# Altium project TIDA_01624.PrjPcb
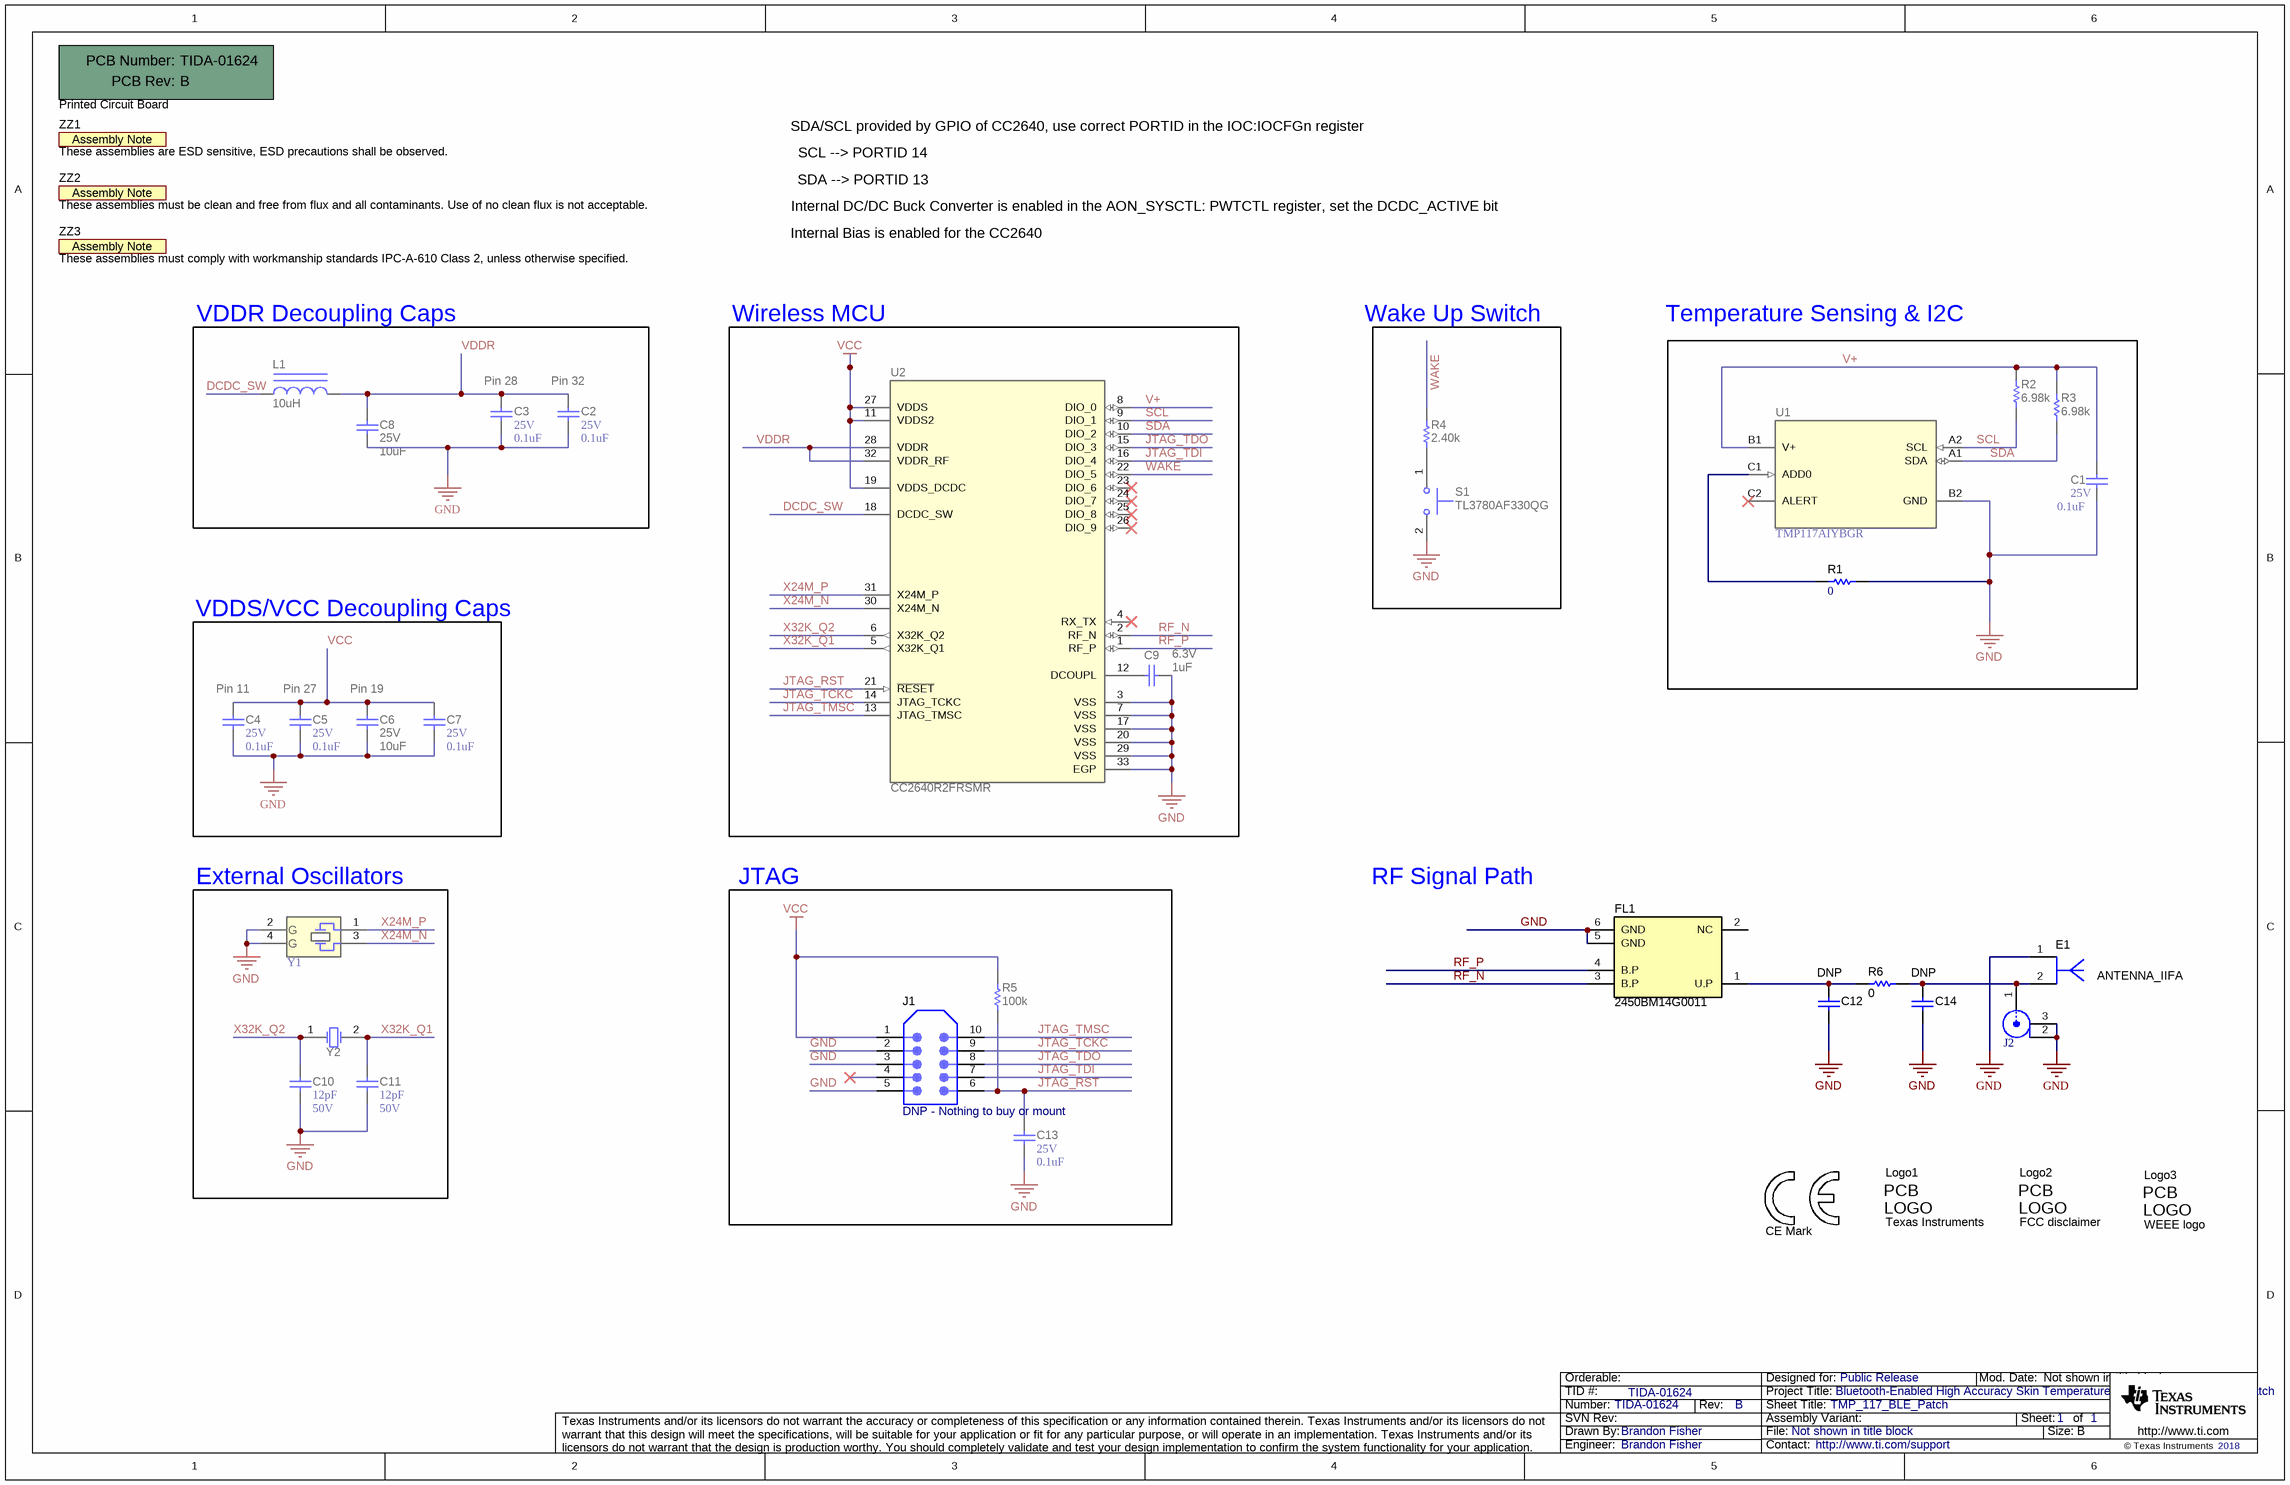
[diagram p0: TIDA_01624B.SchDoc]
CopyrightYear: 2018; PCB_Layout: Brandon Fisher; PCB_Rev: B; PRJ_Customer: Public Release; PRJ_Engineer: Brandon Fisher; PRJ_Number: TIDA-01624; PRJ_Title: Bluetooth-Enabled High Accuracy Skin Temperature Measurement Flex PCB Patch; SCH_Rev: B; TechSupport: http://www.ti.com/support; TID: TIDA-01624
1 sheet, 38 parts. Net scope: global (net labels, ports and power ports of the same name join across sheets).
Board file: TIDA_01624B.PcbDoc

## Sheet TIDA_01624B.SchDoc: TMP_117_BLE_Patch
size 431 x 279 mm; Date: Not shown in title block; ApprovedBy: Not shown in title block; CheckedBy: Not shown in title block; Author: Not shown in title block; CompanyName: Not shown in title block; DrawnBy: Brandon Fisher; Engineer: Not shown in title block; Organization: Not shown in title block; Address1: Not shown in title block; Address2: Not shown in title block; Address3: Not shown in title block; Address4: Not shown in title block; DocumentNumber: 1; Revision: Use project parameter SCH_Rev; SheetNumber: 1; SheetTotal: 1; PageSetup: Record=PageOptions¦CenterHorizontal=True¦CenterVertical=True¦PrintScale=1.00¦XCorrection=1.00¦YCorrection=1.00¦PrintKind=0¦BorderSize=5000000¦LeftOffset=0¦BottomOffset=0¦Orientation=2¦PaperLength=1000¦PaperWidth=1000¦Scale=100¦PaperSource=15¦PrintQuality=600¦MediaType=1¦DitherType=10¦PaperKind=Letter¦PrintScaleMode=1

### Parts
!PCB1  Printed Circuit Board  (mechanical)
C1  VDC_V: 25V  ValueDisplayed: 0.1uF  [0402]  (hidden comment: GRM155R71E104KE14D)
C2  VDC_V: 25V  ValueDisplayed: 0.1uF  [0402]  (hidden comment: GRM155R71E104KE14D)
C3  VDC_V: 25V  ValueDisplayed: 0.1uF  [0402]  (hidden comment: GRM155R71E104KE14D)
C4  VDC_V: 25V  ValueDisplayed: 0.1uF  [0402]  (hidden comment: GRM155R71E104KE14D)
C5  VDC_V: 25V  ValueDisplayed: 0.1uF  [0402]  (hidden comment: GRM155R71E104KE14D)
C6  VDC_V: 25V  ValueDisplayed: 10uF  [0603]  (hidden comment: C1608X5R1E106M080AC)
C7  VDC_V: 25V  ValueDisplayed: 0.1uF  [0402]  (hidden comment: GRM155R71E104KE14D)
C8  VDC_V: 25V  ValueDisplayed: 10uF  [0603]  (hidden comment: C1608X5R1E106M080AC)
C9  VDC_V: 6.3V  ValueDisplayed: 1uF  [0402]  (hidden comment: GRM152R60J105ME15D)
C10  ValueDisplayed: 12pF  VDC_V: 50V  [0201]  (hidden comment: Capacitor)
C11  ValueDisplayed: 12pF  VDC_V: 50V  [0201]  (hidden comment: Capacitor)
C12  DNP  [0201_033]
C13  VDC_V: 25V  ValueDisplayed: 0.1uF  [0402]  (hidden comment: GRM155R71E104KE14D)
C14  DNP  [0201_033]
E1  ANTENNA_IIFA  [ANTENNA_IIFA]  (net tie)
FL1  2450BM14G0011  [Johanson_2450BM14G0011]
J1  DNP - Nothing to buy or mount  [Tag_TC2050-NL]  (no BOM)
J2  U.FL-R-SMT-1(01)  [CONN_UFL-R-SMT-1]  (value not drawn)
L1  ValueDisplayed: 10uH  [0805_HV]  (hidden comment: CKS2125100M-T)
Logo1  Texas Instruments  [TI_Symbol_Overlay_Small]  (no BOM)
Logo2  FCC disclaimer  [FCC_disclaimer]  (no BOM)
Logo3  WEEE logo  [WEEE_Minimum]  (no BOM)
Logo4  CE Mark  [CE_Mark_5mm]  (no BOM)
R1  ValueDisplayed: 0  [0402L]  (hidden comment: RC0402JR-070RL)
R2  ValueDisplayed: 6.98k  [0603]  (hidden comment: RC0603FR-076K98L)
R3  ValueDisplayed: 6.98k  [0603]  (hidden comment: RC0603FR-076K98L)
R4  ValueDisplayed: 2.40k  [0402]  (hidden comment: ERJ-2RKF2401X)
R5  ValueDisplayed: 100k  [0402]  (hidden comment: ERJ-2RKF1003X)
R6  ValueDisplayed: 0  [0201]  (hidden comment: CRCW02010000Z0ED)
S1  TL3780AF330QG  [SW_TL3780]
U1  TMP117AIYBGR  [YBG0006AJAP]
U2  CC2640R2FRSMR  [RSM0032B_NV]
Y1  TSX-3225 24.0000MF15X-AC3  [EPSON_TSX-3225]  (value not drawn)
Y2  CM2012H32768DZFT  [CM2012H]  (value not drawn)
ZZ1  These assemblies are ESD sensitive, ESD precautions shall be observed.  [AssemblyNote]  (no BOM)
ZZ2  These assemblies must be clean and free from flux and all contaminants. Use of no clean flux is not acceptable.  [AssemblyNote]  (no BOM)
ZZ3  These assemblies must comply with workmanship standards IPC-A-610 Class 2, unless otherwise specified.  [AssemblyNote]  (no BOM)

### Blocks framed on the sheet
VDDR Decoupling Caps: C2 C3 C8 L1
Wireless MCU: C9 U2
Wake Up Switch: R4 S1
VDDS/VCC Decoupling Caps: C4-C7
External Oscillators: C10 C11 Y1 Y2
JTAG: C13 J1 R5

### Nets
GND: C1.2 C2.1 C3.1 C4.1 C5.1 C6.2 C7.2 C8.2 C9.1 C10.2 C11.2 C12.2 C13.2 C14.2 E1.1 FL1.5(GND) FL1.6(GND) J1.2 J1.3 J1.5 J2.2 J2.3 R1.2 S1.2 U1.B2(GND) U2.3(VSS) U2.7(VSS) U2.17(VSS) U2.20(VSS) U2.29(VSS) U2.33(EGP) Y1.2(GND) Y1.4(GND)
VCC: C4.2 C5.2 C6.1 C7.1 J1.1 R5.2 U2.11(VDDS2) U2.19(VDDS_DCDC) U2.27(VDDS)
DCDC_SW: L1.1 U2.18(DCDC_SW)
JTAG_RST: C13.1 J1.6 R5.1 U2.21(~{RESET})
JTAG_TCKC: J1.9 U2.14(JTAG_TCKC)
JTAG_TDI: J1.7 U2.16(DIO_4)
JTAG_TDO: J1.8 U2.15(DIO_3)
JTAG_TMSC: J1.10 U2.13(JTAG_TMSC)
RF_N: FL1.3(B.P) U2.2(RF_N)
RF_P: FL1.4(B.P) U2.1(RF_P)
SCL: R2.1 U1.A2(SCL) U2.9(DIO_1)
SDA: R3.1 U1.A1(SDA) U2.10(DIO_2)
V+: C1.1 R2.2 R3.2 U1.B1(V+) U2.8(DIO_0)
VDDR: C2.2 C3.2 C8.1 L1.2 U2.28(VDDR) U2.32(VDDR_RF)
WAKE: R4.1 U2.22(DIO_5)
X24M_N: U2.30(X24M_N) Y1.3
X24M_P: U2.31(X24M_P) Y1.1
X32K_Q1: C11.1 U2.5(X32K_Q1) Y2.2(OSC2)
X32K_Q2: C10.1 U2.6(X32K_Q2) Y2.1(OSC1)
NetC9_2: C9.2 U2.12(DCOUPL)
NetC12_1: C12.1 FL1.1(U.P) R6.1
NetC14_1: C14.1 E1.2 J2.1 R6.2
NetR1_1: R1.1 U1.C1(ADD0)
NetR4_2: R4.2 S1.1

Not connected (* = marked no-connect by the designer): FL1 2(NC); J1 4*; U1 C2(ALERT)*; U2 4(RX_TX)* 23(DIO_6)* 24(DIO_7)* 25(DIO_8)* 26(DIO_9)*

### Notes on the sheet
- SCL --> PORTID 14
- SDA/SCL provided by GPIO of CC2640, use correct PORTID in the IOC:IOCFGn register
- SDA --> PORTID 13
- Internal Bias is enabled for the CC2640
- Internal DC/DC Buck Converter is enabled in the AON_SYSCTL: PWTCTL register, set the DCDC_ACTIVE bit
- Temperature Sensing & I2C
- (near C3) Pin 28
- (near C2) Pin 32
- (near C4) Pin 11
- (near C5) Pin 27
- (near C6) Pin 19
- RF Signal Path

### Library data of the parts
!PCB1 = CMP-0003618-2: Manufacturer: Any; PartNumber: TIDA-01624
C1-C5 C7 C13 = CMP-0006659-2: CAP, CERM, 0.1 uF, 25 V, +/- 10%, X7R, 0402; Manufacturer: MuRata; TaMin_C: -55°C; Polarized: N; SizeAreaWB_mm2: 3; Value1: Unknown; U/M: EA; Value: 0.1uF; TaMax_C: 125°C; SizeZ_mm: 0.6; SizeX_mm: 1; SizeY_mm: 0.5; CompType: Capacitor; Cap_F: 100nF; AEC Category: Q200
C6 = CMP-0007007-5: CAP, CERM, 10 uF, 25 V, +/- 20%, X5R, 0603; Manufacturer: TDK; TaMin_C: -55°C; Polarized: N; SizeAreaWB_mm2: 4.68; Value1: 0.004639 ohm; U/M: EA; Value: 10uF; TaMax_C: 85°C; SizeZ_mm: 1; SizeX_mm: 1.6; SizeY_mm: 0.8; SizeArea_mm2: 1.28; CompType: Capacitor; Cap_F: 10µF; AEC Category: Q200; ESR_ohm: 4.639m; IRMS_A: 2.41407A
C8 = CMP-0007007-5: CAP, CERM, 10 uF, 25 V, +/- 20%, X5R, 0603; Manufacturer: TDK; TaMin_C: -55°C; Polarized: N; SizeAreaWB_mm2: 4.68; Value1: 0.004639 ohm; U/M: EA; Value: 10uF; TaMax_C: 85°C; SizeZ_mm: 1; SizeX_mm: 1.6; SizeY_mm: 0.8; SizeArea_mm2: 1.28; Cap_F: 10µF; AEC Category: Q200; ESR_ohm: 4.639m; IRMS_A: 2.41407A
C9 = CMP-0006372-2: CAP, CERM, 1 uF, 6.3 V, +/- 20%, X5R, 0402; Manufacturer: MuRata; TaMin_C: -55°C; Polarized: N; SizeAreaWB_mm2: 3; Value1: Unknown; U/M: EA; Value: 1uF; TaMax_C: 85°C; SizeZ_mm: 0.6; SizeX_mm: 1; SizeY_mm: 0.5; CompType: Capacitor; Cap_F: 1µF; AEC Category: Q200
C10 C11 = CMP-0009664-3: CAP, CERM, 12 pF, 50 V, +/- 5%, C0G/NP0, 0201; PartNumber: GRM0335C1H120JA01D; Manufacturer: MuRata; Polarized: N; Value: 12pF; U/M: EA; Value1: Unknown; TaMin_C: -55°C; TaMax_C: 125°C; SizeArea_mm2: 0.18; SizeAreaWB_mm2: 2.08; SizeX_mm: 0.6; SizeY_mm: 0.3; SizeZ_mm: 0.26; AEC Category: Q200
C12 C14 = CMP-0009654-3: CAP, CERM, 470 pF, 50 V, +/- 10%, X7R, AEC-Q200 Grade 1, 0201; SizeAreaWB_mm2: 2.08; U/M: EA; SizeZ_mm: 0.33; SizeX_mm: 0.6; SizeY_mm: 0.3; SizeArea_mm2: 0.18
E1 = CMP-0001736-1: PCB Antenna.  There is nothing to buy or mount.
FL1 = CMP-0001890-2: 2.4GHz Impedance Matched Balun + embedded FCC/ETSI Band Pass Filter, SMD; Manufacturer: Johanson Technology; SizeZ_mm: 0.7; SizeX_mm: 1.6; SizeY_mm: 0.8; SizeAreaWB_mm2: 4.68; SizeArea_mm2: 1.28
J1 = CMP-0075101-1: Footprint for Tag-Connect TC2050 No-Legs cables; PartNumber: TC2050-IDC-NL-FP; Note: Footprint only, to mate with Tag-Connect TC2050 No-Legs cables; CT: False; CompType: Receptacle
J2 = CMP-0075320-1: Receptacle, Ultra Miniature Coaxial, Male Pin, 50 ohm, SMT; Manufacturer: Hirose Electric Co. Ltd.; CNHeader: False; Gender: Female; ContactFinish: Gold
L1 = CMP-0059606-1: Inductor, Multilayer, Ferrite, 10 uH, 0.11 A, 0.52 ohm, SMD; Manufacturer: Taiyo Yuden; Green_Lifecycle: Active; SizeAreaWB_mm2: 6.75; DCR_ohm: 5.2d; Green_REACh: Passed; Value: 10uH; Imax_A: 1.1dA; SizeZ_mm: 1.45; SizeX_mm: 2; SizeY_mm: 1.25; Value2: 0.11A; SizeArea_mm2: 2.5; Ind_H: 10µH; AEC Category: Q200
Logo1 = CMP-0074838-1: Texas Instrument Corporate Signature; SymbolCreator: a0412235; Lib Reference: TI_Logo
Logo2 = CMP-0074847-1: FCC_disclaimer
Logo3 = CMP-0074769-1
Logo4 = CMP-0074844-1: SymbolCreator: a0412235
R1 = CMP-0027004-2: RES, 0, 5%, 0.063 W, 0402; Manufacturer: Yageo America; Power_W: 63mW; TempCo: 200 ppm/C; Value_Code: 0000; U/M: EA; Value: 0; EIA_Code: E24; SizeX_mm: 1; SizeY_mm: 0.5; SizeZ_mm: 0.6; Value2: 0.063W; VDC_V: 50V; AEC Category: Q200
R2 R3 = CMP-0023254-3: RES, 6.98 k, 1%, 0.1 W, 0603; Manufacturer: Yageo America; Power_W: 100mW; TempCo: 200 ppm/C; Value_Code: 6k98; U/M: EA; Value: 6.98k; EIA_Code: E96; SizeX_mm: 1.6; SizeY_mm: 0.8; SizeZ_mm: 1; Value2: 0.1W; SizeArea_mm2: 1.28; VDC_V: 150V; AEC Category: Q200
R4 = CMP-0026685-1: RES, 2.40 k, 1%, 0.1 W, AEC-Q200 Grade 0, 0402; Manufacturer: Panasonic; Power_W: 100mW; TempCo: 100 ppm/C; Value_Code: 2k40; U/M: EA; Value: 2.40k; Res_ohm: 2.4k; SizeX_mm: 1; SizeY_mm: 0.5; SizeZ_mm: 0.6; Value2: 0.1W; CompType: Resistor; AEC Qualified: Y; AEC Grade: 0; AEC Category: Q200
R5 = CMP-0026659-1: RES, 100 k, 1%, 0.1 W, 0402; Manufacturer: Panasonic; Power_W: 100mW; TempCo: 100 ppm/C; U/M: EA; Value: 100k; EIA_Code: E96; SizeX_mm: 1; SizeY_mm: 0.5; SizeZ_mm: 0.6; Value2: 0.1W; VDC_V: 50V; AEC Category: Q200
R6 = CMP-0027008-4: RES, 0, 5%, 0.05 W, 0201; Manufacturer: Vishay-Dale; Power_W: 50mW; TempCo: ppm/C; Value_Code: 0000; Value: 0; EIA_Code: E24; SizeX_mm: 0.6; SizeY_mm: 0.3; SizeZ_mm: 0.26; Value2: 0.05W; SizeArea_mm2: 0.18; AEC Qualified: N; AEC Category: Q200
S1 = CMP-0084104-1: Switch, SPST-NO, 0.05 A, 12 VDC, SMT; Manufacturer: E-Switch; CurrentRating_mA: 50A; SizeAreaWB_mm2: 13.5; PositionCount: 1; SizeZ_mm: 0.7; SizeX_mm: 3.5; SizeY_mm: 2; SwitchFunction: Off-Mom; SizeArea_mm2: 7; VDC_V: 12V
U1 = CMP-0860099-1: ±0.1°C accurate digital temperature sensor with integrated NV memory, YBG0006AJAP (DSBGA-6); Alternate Manufacturer: Texas Instruments; Alternate PartNumber: TMP117AIYBGT; SizeArea_mm2: 2.0049; SizeZ_mm: 0.5; SizeY_mm: 1.63; SizeX_mm: 1.23; AEC Qualified: N; SizeAreaWB_mm2: 5.8649; AEC Category: Q200; CompType: IC; Rating: Catalog
U2 = CMP-0076686-1: SimpleLink(TM) Bluetooth(R) low energy Wireless MCU, RSM0032B (VQFN-32); Manufacturer: Texas Instruments; Alternate PartNumber: CC2640R2FRSMT; SizeAreaWB_mm2: 25.0; SizeArea_mm2: 16.0; SizeZ_mm: 1.0; SizeY_mm: 4.0; U/M: EA; CompType: IC
Y1 = CMP-0079304-1: Crystal, 24 MHz, 10 ppm, 9 pF, SMD; Manufacturer: Epson; TaMin_C: -40°C; Frequency Stability: 15 ppm; Frequency_Fixed: 24MHz; TaMax_C: 85°C; AEC Category: Q200; AEC Qualified: N; Frequency Tolerance: 10 ppm; Load Capacitance: 9 pF
Y2 = CMP-0004654-3: Crystal, 32.768 kHz, SMD; Manufacturer: Citizen Electronics; TaMax_C: 85°C; TaMin_C: -40°C; Frequency Stability: +/-20ppm
ZZ1 = CMP-0077236-1
ZZ2 = CMP-0077237-1
ZZ3 = CMP-0077238-1

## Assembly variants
001: not fitted C12 C14 J1 J1 J2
